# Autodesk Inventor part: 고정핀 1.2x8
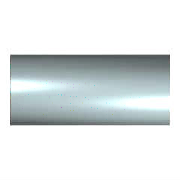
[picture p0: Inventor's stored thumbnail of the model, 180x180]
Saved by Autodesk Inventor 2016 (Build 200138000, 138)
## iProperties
IsCustomPart: 1
Created: 2012-02
Part Number: 고정핀 1.2x8
Material: 강철, 연강
Description: 평행 핀
Document SubType Name: Modeling
Standard: KS B 1320
Designer: P15F
Standards Organization: KS
Language: ko-KR
Size Designation: C 1.2 x  8
Categories: <MemberInstance><Categories><Category DisplayName="조임쇠" InternalName="e4da775c-781d-43d5-af7c-5136215cf5a6" Mnemonic="FSTN"><Category DisplayName="핀" InternalNa
Density: 1 g/cm^3
Appearance: 노란색
Author: P15F
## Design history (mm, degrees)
sketch "스케치1"
  geometry: C1 r 0.6 at (0, 0); 1 further point
  constraints: 1 centre point, 1 coincident
  dimensions: "d1" = 1.2 diameter of C1 (= NND)
extrude "본체" new body sketch "스케치1" distance "d2" = 8 (= NLG); taper "d3" = 0 deg
node "작업 평면1"
sketch "스케치3"
  geometry: 1 further point
body "Solid1"
other parameters: "NND" = 1.2 [user parameter; used in 1 equation term], "NLG" = 8 [user parameter; used in 1 equation term], "d8" = 0, "d9" = 0, "d10" = 0
